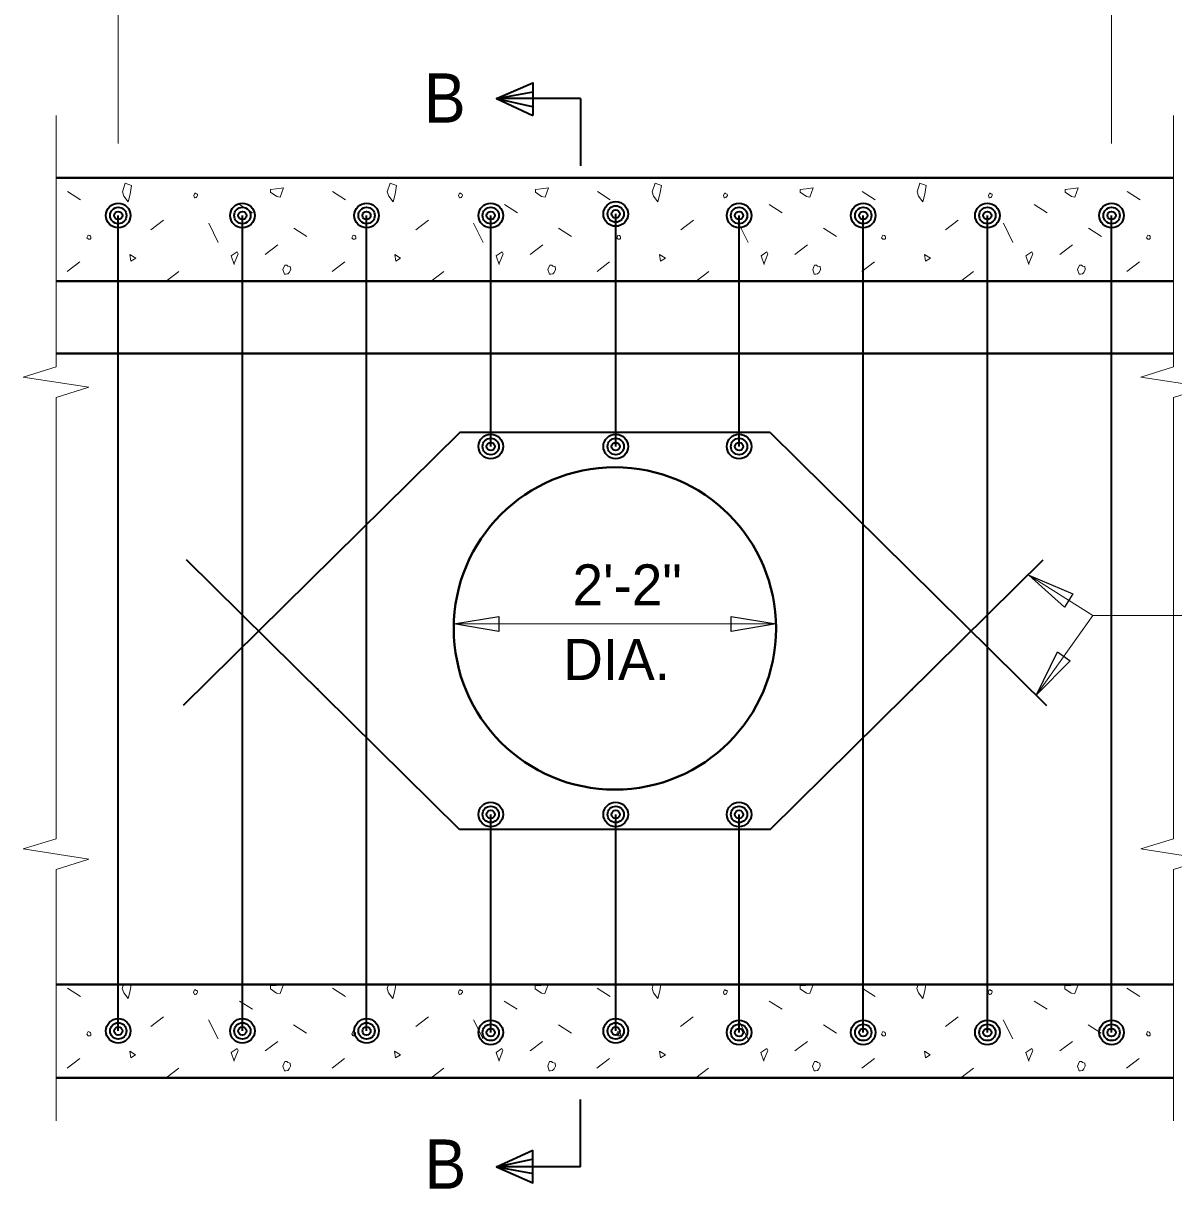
# Model space of a CAD drawing. Extents: x 0 to 34, y 0 to 23.4.
# Drawn here: x 25.268 to 29.648, y 4.725 to 9.162 of the extents above; entities that cross this region are included whole.
import ezdxf
from ezdxf.enums import TextEntityAlignment as Align

# ---------------------------------------------------------------- set-up
doc = ezdxf.new("R2010")
doc.units = 0
doc.header["$LTSCALE"] = 0.062
for name, color, linetype, lineweight in [('1', 7, 'Continuous', 40), ('3', 7, 'Continuous', 35), ('4', 7, 'Continuous', 13), ('7', 7, 'Continuous', 13)]:
    doc.layers.add(name, color=color, linetype=linetype, lineweight=lineweight)

msp = doc.modelspace()

# ---------------------------------------------------------------- linework, layer by layer
at = {"layer": '1', "lineweight": 13}
for p, q in [((25.39328, 7.85406), (25.39328, 8.81109)), ((29.6476, 7.85406), (29.6476, 8.81109)), ((25.39328, 6.05719), (25.39328, 7.73688)), ((29.6476, 6.05719), (29.6476, 7.73688)), ((25.39328, 4.98297), (25.39328, 5.94)), ((29.6476, 4.98297), (29.6476, 5.94))]:
    msp.add_line(p, q, dxfattribs=at)
at = {"layer": '1'}
for p, q in [((25.39328, 8.57406), (29.6476, 8.57406)), ((25.3937, 8.18005), (29.6476, 8.18005)), ((29.64682, 8.18005), (27.52672, 8.18005)), ((25.3937, 7.90438), (27.52042, 7.90438)), ((29.64682, 7.90438), (27.52042, 7.90438)), ((25.39328, 5.50151), (29.6476, 5.50151)), ((25.39328, 5.14703), (29.6476, 5.14703))]:
    msp.add_line(p, q, dxfattribs=at)
at = {"layer": '1', "lineweight": 13}
for points in [[(25.39328, 7.85406), (25.26828, 7.815), (25.51828, 7.77594), (25.39328, 7.73688)], [(29.6476, 7.85406), (29.5226, 7.815), (29.7726, 7.77594), (29.6476, 7.73688)], [(25.39328, 6.05719), (25.26828, 6.01813), (25.51828, 5.97906), (25.39328, 5.94)], [(29.6476, 6.05719), (29.5226, 6.01813), (29.7726, 5.97906), (29.6476, 5.94)]]:
    msp.add_lwpolyline(points, dxfattribs=at)
at = {"layer": '1'}
msp.add_circle((27.52044, 6.85779), 0.61354, dxfattribs=at)
at = {"layer": '3'}
for p, q in [((27.52354, 7.55063), (27.52354, 8.43589)), ((25.62969, 5.32536), (25.62969, 8.4301)), ((26.1024, 5.32536), (26.1024, 8.4301)), ((26.575, 5.32536), (26.575, 8.4301)), ((27.04776, 7.55063), (27.04776, 8.4301)), ((27.99313, 7.55063), (27.99313, 8.4301)), ((28.46583, 5.31958), (28.46583, 8.4301)), ((28.93844, 5.31958), (28.93844, 8.4301)), ((29.4112, 5.31958), (29.4112, 8.4301)), ((26.92964, 7.60354), (25.87693, 6.56458)), ((28.11125, 7.60354), (26.92964, 7.60354)), ((28.11125, 7.60354), (29.16396, 6.56458)), ((26.92943, 6.0924), (25.89005, 7.11849)), ((28.11135, 6.0924), (29.15083, 7.11849)), ((26.39016, 6.62484), (26.38792, 6.62698)), ((28.65073, 6.62484), (28.65292, 6.62698)), ((27.04776, 5.31958), (27.04776, 6.14974)), ((27.52354, 5.32536), (27.52354, 6.14974)), ((27.99313, 5.31958), (27.99313, 6.14974)), ((28.11135, 6.0924), (26.92943, 6.0924))]:
    msp.add_line(p, q, dxfattribs=at)
for centre, radius in [((25.62969, 8.4301), 0.04688), ((26.1024, 8.4301), 0.04688), ((26.575, 8.4301), 0.04688), ((27.04776, 8.4301), 0.04688), ((27.52354, 8.43589), 0.04688), ((27.99313, 8.4301), 0.04688), ((28.46583, 8.4301), 0.04688), ((28.93844, 8.4301), 0.04688), ((29.4112, 8.4301), 0.04688), ((25.62969, 8.4301), 0.03125), ((25.62969, 8.4301), 0.01562), ((26.1024, 8.4301), 0.03125), ((26.1024, 8.4301), 0.01562), ((26.575, 8.4301), 0.03125), ((26.575, 8.4301), 0.01562), ((27.04776, 8.4301), 0.03125), ((27.04776, 8.4301), 0.01562), ((27.52354, 8.43589), 0.03125), ((27.52354, 8.43589), 0.01562), ((27.99313, 8.4301), 0.03125), ((27.99313, 8.4301), 0.01562), ((28.46583, 8.4301), 0.03125), ((28.46583, 8.4301), 0.01562), ((28.93844, 8.4301), 0.03125), ((28.93844, 8.4301), 0.01562), ((29.4112, 8.4301), 0.03125), ((29.4112, 8.4301), 0.01562), ((27.04776, 7.55063), 0.04688), ((27.52354, 7.55063), 0.04688), ((27.99313, 7.55063), 0.04688), ((27.04776, 7.55063), 0.03125), ((27.04776, 7.55063), 0.01562), ((27.52354, 7.55063), 0.03125), ((27.52354, 7.55063), 0.01562), ((27.99313, 7.55063), 0.03125), ((27.99313, 7.55063), 0.01562), ((27.04776, 6.14974), 0.04688), ((27.04776, 6.14974), 0.03125), ((27.52354, 6.14974), 0.04688), ((27.52354, 6.14974), 0.03125), ((27.99313, 6.14974), 0.04688), ((27.99313, 6.14974), 0.03125), ((27.04776, 6.14974), 0.01562), ((27.52354, 6.14974), 0.01562), ((27.99313, 6.14974), 0.01562), ((25.62969, 5.32536), 0.04688), ((26.1024, 5.32536), 0.04688), ((26.575, 5.32536), 0.04688), ((27.52354, 5.32536), 0.04688), ((25.62969, 5.32536), 0.03125), ((25.62969, 5.32536), 0.01562), ((26.1024, 5.32536), 0.03125), ((26.1024, 5.32536), 0.01562), ((26.575, 5.32536), 0.03125), ((26.575, 5.32536), 0.01562), ((27.04776, 5.31958), 0.04688), ((27.04776, 5.31958), 0.03125), ((27.04776, 5.31958), 0.01562), ((27.52354, 5.32536), 0.03125), ((27.52354, 5.32536), 0.01562), ((27.99313, 5.31958), 0.04688), ((27.99313, 5.31958), 0.03125), ((27.99313, 5.31958), 0.01562), ((28.46583, 5.31958), 0.04688), ((28.46583, 5.31958), 0.03125), ((28.46583, 5.31958), 0.01562), ((28.93844, 5.31958), 0.04688), ((28.93844, 5.31958), 0.03125), ((28.93844, 5.31958), 0.01562), ((29.4112, 5.31958), 0.04688), ((29.4112, 5.31958), 0.03125), ((29.4112, 5.31958), 0.01562)]:
    msp.add_circle(centre, radius, dxfattribs=at)
at = {"layer": '4'}
for p, q in [((25.62969, 8.70458), (25.62969, 9.57755)), ((29.4112, 8.70458), (29.4112, 9.57755)), ((29.3401, 6.90651), (29.09609, 7.06089)), ((29.3401, 6.90651), (29.12505, 6.60469)), ((29.3401, 6.90651), (31.06495, 6.90651)), ((26.90703, 6.87505), (28.13385, 6.87505))]:
    msp.add_line(p, q, dxfattribs=at)
at = {"layer": '4', "lineweight": 35}
for p, q in [((27.06964, 8.87526), (27.20891, 8.90104)), ((27.06964, 8.87526), (27.20594, 8.84563)), ((27.38964, 8.87526), (27.38964, 8.61927)), ((27.38964, 4.80771), (27.38964, 5.0637)), ((27.06964, 4.80771), (27.20594, 4.83734)), ((27.06964, 4.80771), (27.20891, 4.78193))]:
    msp.add_line(p, q, dxfattribs=at)
for points in [[(27.06964, 8.87526), (27.20823, 8.93536), (27.20823, 8.81125)], [(27.38964, 8.87526), (27.06964, 8.87526), (27.20823, 8.81125)], [(27.38964, 4.80771), (27.06964, 4.80771), (27.20823, 4.87172)], [(27.06964, 4.80771), (27.20823, 4.7476), (27.20823, 4.87172)]]:
    msp.add_lwpolyline(points, dxfattribs=at)
at = {"layer": '4', "lineweight": 25}
for points in [[(29.26427, 6.99), (29.23219, 6.93927), (29.09609, 7.06089)], [(27.07802, 6.90354), (27.07802, 6.84656), (26.90703, 6.87505)], [(27.96286, 6.84656), (27.96286, 6.90354), (28.13385, 6.87505)], [(29.20505, 6.7687), (29.25396, 6.73385), (29.12505, 6.60469)]]:
    msp.add_lwpolyline(points, close=True, dxfattribs=at)
at = {"layer": '7'}
for p, q in [((25.43682, 8.52109), (25.48625, 8.48979)), ((26.44521, 8.52109), (26.49464, 8.48979)), ((27.45359, 8.52109), (27.50302, 8.48979)), ((28.46198, 8.52109), (28.51141, 8.48979)), ((29.47036, 8.52109), (29.51979, 8.48979)), ((26.09151, 8.47203), (26.14099, 8.44078)), ((27.0999, 8.47203), (27.14938, 8.44078)), ((28.10828, 8.47203), (28.15776, 8.44078)), ((29.11667, 8.47203), (29.16615, 8.44078)), ((25.80245, 8.41234), (25.75432, 8.37573)), ((25.97401, 8.40125), (26.01068, 8.32771)), ((26.81083, 8.41234), (26.76271, 8.37573)), ((26.9824, 8.40125), (27.01906, 8.32771)), ((27.81922, 8.41234), (27.77109, 8.37573)), ((27.99078, 8.40125), (28.02745, 8.32771)), ((28.8276, 8.41234), (28.77948, 8.37573)), ((28.99917, 8.40125), (29.03583, 8.32771)), ((26.29786, 8.38172), (26.34734, 8.35047)), ((27.30625, 8.38172), (27.35573, 8.35047)), ((28.31464, 8.38172), (28.36411, 8.35047)), ((29.32302, 8.38172), (29.3725, 8.35047)), ((26.2374, 8.31859), (26.18927, 8.28198)), ((27.24578, 8.31859), (27.19766, 8.28198)), ((28.25417, 8.31859), (28.20604, 8.28198)), ((29.26255, 8.31859), (29.21443, 8.28198)), ((25.48365, 8.25359), (25.43552, 8.21698)), ((26.49203, 8.25359), (26.44391, 8.21698)), ((27.50042, 8.25359), (27.45229, 8.21698)), ((28.5088, 8.25359), (28.46068, 8.21698)), ((29.51719, 8.25359), (29.46906, 8.21698)), ((25.86078, 8.21667), (25.81266, 8.18005)), ((26.86917, 8.21667), (26.82104, 8.18005)), ((27.87755, 8.21667), (27.82943, 8.18005)), ((28.88594, 8.21667), (28.83781, 8.18005)), ((25.43641, 5.48807), (25.48583, 5.45677)), ((26.25344, 5.50151), (26.23083, 5.49854)), ((26.44479, 5.48807), (26.49422, 5.45677)), ((27.26182, 5.50151), (27.23922, 5.49854)), ((27.45318, 5.48807), (27.5026, 5.45677)), ((28.27021, 5.50151), (28.2476, 5.49854)), ((28.46156, 5.48807), (28.51099, 5.45677)), ((29.27859, 5.50151), (29.25599, 5.49854)), ((29.46995, 5.48807), (29.51938, 5.45677)), ((26.09109, 5.43901), (26.14057, 5.40776)), ((27.09948, 5.43901), (27.14896, 5.40776)), ((28.10786, 5.43901), (28.15734, 5.40776)), ((29.11625, 5.43901), (29.16573, 5.40776)), ((25.80203, 5.37932), (25.75391, 5.34271)), ((26.81042, 5.37932), (26.76229, 5.34271)), ((27.8188, 5.37932), (27.77068, 5.34271)), ((28.82719, 5.37932), (28.77906, 5.34271)), ((25.97359, 5.36823), (26.01026, 5.29469)), ((26.29745, 5.3487), (26.34693, 5.31745)), ((26.98198, 5.36823), (27.01865, 5.29469)), ((27.30583, 5.3487), (27.35531, 5.31745)), ((27.99036, 5.36823), (28.02703, 5.29469)), ((28.31422, 5.3487), (28.3637, 5.31745)), ((28.99875, 5.36823), (29.03542, 5.29469)), ((29.3226, 5.3487), (29.37208, 5.31745)), ((26.23698, 5.28557), (26.18885, 5.24896)), ((27.24536, 5.28557), (27.19724, 5.24896)), ((28.25375, 5.28557), (28.20563, 5.24896)), ((29.26214, 5.28557), (29.21401, 5.24896)), ((25.48323, 5.22057), (25.4351, 5.18396)), ((26.49161, 5.22057), (26.44349, 5.18396)), ((27.5, 5.22057), (27.45188, 5.18396)), ((28.50839, 5.22057), (28.46026, 5.18396)), ((29.51677, 5.22057), (29.46865, 5.18396)), ((25.86036, 5.18365), (25.81224, 5.14703)), ((26.86875, 5.18365), (26.82063, 5.14703)), ((27.87714, 5.18365), (27.82901, 5.14703)), ((28.88552, 5.18365), (28.8374, 5.14703))]:
    msp.add_line(p, q, dxfattribs=at)
for points in [[(25.65661, 8.55349), (25.64542, 8.52036), (25.65109, 8.5038), (25.66766, 8.48167), (25.675, 8.51115), (25.68052, 8.54432)], [(26.23125, 8.53156), (26.20917, 8.52969), (26.20917, 8.51865), (26.23313, 8.50214), (26.24609, 8.50026), (26.25901, 8.53521)], [(26.665, 8.55349), (26.6538, 8.52036), (26.65948, 8.5038), (26.67604, 8.48167), (26.68339, 8.51115), (26.68891, 8.54432)], [(27.23964, 8.53156), (27.21755, 8.52969), (27.21755, 8.51865), (27.24151, 8.50214), (27.25448, 8.50026), (27.2674, 8.53521)], [(27.67339, 8.55349), (27.66219, 8.52036), (27.66786, 8.5038), (27.68443, 8.48167), (27.69177, 8.51115), (27.69729, 8.54432)], [(28.24802, 8.53156), (28.22594, 8.52969), (28.22594, 8.51865), (28.2499, 8.50214), (28.26286, 8.50026), (28.27578, 8.53521)], [(28.68177, 8.55349), (28.67057, 8.52036), (28.67625, 8.5038), (28.69281, 8.48167), (28.70016, 8.51115), (28.70568, 8.54432)], [(29.25641, 8.53156), (29.23432, 8.52969), (29.23432, 8.51865), (29.25828, 8.50214), (29.27125, 8.50026), (29.28417, 8.53521)], [(25.91703, 8.50625), (25.91995, 8.49703), (25.9226, 8.49703), (25.92635, 8.49797), (25.92906, 8.50063), (25.93172, 8.50625), (25.93099, 8.51177), (25.92635, 8.51271), (25.92438, 8.51464), (25.92073, 8.51464)], [(26.92542, 8.50625), (26.92833, 8.49703), (26.93099, 8.49703), (26.93474, 8.49797), (26.93745, 8.50063), (26.9401, 8.50625), (26.93938, 8.51177), (26.93474, 8.51271), (26.93276, 8.51464), (26.92911, 8.51464)], [(27.9338, 8.50625), (27.93672, 8.49703), (27.93938, 8.49703), (27.94313, 8.49797), (27.94583, 8.50063), (27.94849, 8.50625), (27.94776, 8.51177), (27.94313, 8.51271), (27.94115, 8.51464), (27.9375, 8.51464)], [(28.94219, 8.50625), (28.9451, 8.49703), (28.94776, 8.49703), (28.95151, 8.49797), (28.95422, 8.50063), (28.95688, 8.50625), (28.95615, 8.51177), (28.95151, 8.51271), (28.94953, 8.51464), (28.94589, 8.51464)], [(25.5151, 8.35562), (25.51047, 8.34547), (25.51589, 8.33984), (25.5225, 8.33984), (25.52521, 8.34281), (25.52521, 8.34823), (25.52432, 8.35089), (25.52146, 8.35385)], [(26.52349, 8.35562), (26.51885, 8.34547), (26.52427, 8.33984), (26.53089, 8.33984), (26.53359, 8.34281), (26.53359, 8.34823), (26.53271, 8.35089), (26.52984, 8.35385)], [(27.53188, 8.35562), (27.52724, 8.34547), (27.53266, 8.33984), (27.53927, 8.33984), (27.54198, 8.34281), (27.54198, 8.34823), (27.54109, 8.35089), (27.53823, 8.35385)], [(28.54026, 8.35562), (28.53563, 8.34547), (28.54104, 8.33984), (28.54766, 8.33984), (28.55036, 8.34281), (28.55036, 8.34823), (28.54948, 8.35089), (28.54661, 8.35385)], [(29.54865, 8.35562), (29.54401, 8.34547), (29.54943, 8.33984), (29.55604, 8.33984), (29.55875, 8.34281), (29.55875, 8.34823), (29.55786, 8.35089), (29.555, 8.35385)], [(25.67401, 8.28188), (25.67771, 8.25604), (25.6962, 8.26714)], [(26.06005, 8.27646), (26.07146, 8.24323), (26.07146, 8.24682), (26.08615, 8.2838), (26.0824, 8.29115)], [(26.6824, 8.28188), (26.68609, 8.25604), (26.70458, 8.26714)], [(27.06844, 8.27646), (27.07984, 8.24323), (27.07984, 8.24682), (27.09453, 8.2838), (27.09078, 8.29115)], [(27.69078, 8.28188), (27.69448, 8.25604), (27.71297, 8.26714)], [(28.07682, 8.27646), (28.08823, 8.24323), (28.08823, 8.24682), (28.10292, 8.2838), (28.09917, 8.29115)], [(28.69917, 8.28188), (28.70286, 8.25604), (28.72135, 8.26714)], [(29.08521, 8.27646), (29.09661, 8.24323), (29.09661, 8.24682), (29.1113, 8.2838), (29.10755, 8.29115)], [(26.25667, 8.22474), (26.2625, 8.2063), (26.26781, 8.2063), (26.27531, 8.20813), (26.28073, 8.21349), (26.28609, 8.22474), (26.28458, 8.23568), (26.27531, 8.2376), (26.27141, 8.24141), (26.26406, 8.24141)], [(27.26505, 8.22474), (27.27089, 8.2063), (27.2762, 8.2063), (27.2837, 8.20813), (27.28911, 8.21349), (27.29448, 8.22474), (27.29297, 8.23568), (27.2837, 8.2376), (27.27979, 8.24141), (27.27245, 8.24141)], [(28.27344, 8.22474), (28.27927, 8.2063), (28.28458, 8.2063), (28.29208, 8.20813), (28.2975, 8.21349), (28.30286, 8.22474), (28.30135, 8.23568), (28.29208, 8.2376), (28.28818, 8.24141), (28.28083, 8.24141)], [(29.28182, 8.22474), (29.28766, 8.2063), (29.29297, 8.2063), (29.30047, 8.20813), (29.30589, 8.21349), (29.31125, 8.22474), (29.30974, 8.23568), (29.30047, 8.2376), (29.29656, 8.24141), (29.28922, 8.24141)], [(25.91661, 5.47323), (25.91953, 5.46401), (25.92219, 5.46401), (25.92594, 5.46495), (25.92865, 5.4676), (25.9313, 5.47323), (25.93057, 5.47875), (25.92594, 5.47969), (25.92396, 5.48161), (25.92031, 5.48161)], [(26.925, 5.47323), (26.92792, 5.46401), (26.93057, 5.46401), (26.93432, 5.46495), (26.93703, 5.4676), (26.93969, 5.47323), (26.93896, 5.47875), (26.93432, 5.47969), (26.93234, 5.48161), (26.9287, 5.48161)], [(27.93339, 5.47323), (27.9363, 5.46401), (27.93896, 5.46401), (27.94271, 5.46495), (27.94542, 5.4676), (27.94807, 5.47323), (27.94734, 5.47875), (27.94271, 5.47969), (27.94073, 5.48161), (27.93708, 5.48161)], [(28.94177, 5.47323), (28.94469, 5.46401), (28.94734, 5.46401), (28.95109, 5.46495), (28.9538, 5.4676), (28.95646, 5.47323), (28.95573, 5.47875), (28.95109, 5.47969), (28.94911, 5.48161), (28.94547, 5.48161)], [(25.51469, 5.3226), (25.51005, 5.31245), (25.51547, 5.30682), (25.52208, 5.30682), (25.52479, 5.30979), (25.52479, 5.31521), (25.52391, 5.31786), (25.52104, 5.32083)], [(26.52307, 5.3226), (26.51844, 5.31245), (26.52385, 5.30682), (26.53047, 5.30682), (26.53318, 5.30979), (26.53318, 5.31521), (26.53229, 5.31786), (26.52943, 5.32083)], [(27.53146, 5.3226), (27.52682, 5.31245), (27.53224, 5.30682), (27.53885, 5.30682), (27.54156, 5.30979), (27.54156, 5.31521), (27.54068, 5.31786), (27.53781, 5.32083)], [(28.53984, 5.3226), (28.53521, 5.31245), (28.54063, 5.30682), (28.54724, 5.30682), (28.54995, 5.30979), (28.54995, 5.31521), (28.54906, 5.31786), (28.5462, 5.32083)], [(29.54823, 5.3226), (29.54359, 5.31245), (29.54901, 5.30682), (29.55563, 5.30682), (29.55833, 5.30979), (29.55833, 5.31521), (29.55745, 5.31786), (29.55458, 5.32083)], [(25.67359, 5.24885), (25.67729, 5.22302), (25.69578, 5.23411)], [(26.05964, 5.24344), (26.07104, 5.21021), (26.07104, 5.2138), (26.08573, 5.25078), (26.08198, 5.25813)], [(26.68198, 5.24885), (26.68568, 5.22302), (26.70417, 5.23411)], [(27.06802, 5.24344), (27.07943, 5.21021), (27.07943, 5.2138), (27.09411, 5.25078), (27.09036, 5.25813)], [(27.69036, 5.24885), (27.69406, 5.22302), (27.71255, 5.23411)], [(28.07641, 5.24344), (28.08781, 5.21021), (28.08781, 5.2138), (28.1025, 5.25078), (28.09875, 5.25813)], [(28.69875, 5.24885), (28.70245, 5.22302), (28.72094, 5.23411)], [(29.08479, 5.24344), (29.0962, 5.21021), (29.0962, 5.2138), (29.11089, 5.25078), (29.10714, 5.25813)], [(26.25625, 5.19172), (26.26208, 5.17328), (26.2674, 5.17328), (26.2749, 5.1751), (26.28031, 5.18047), (26.28568, 5.19172), (26.28417, 5.20266), (26.2749, 5.20458), (26.27099, 5.20839), (26.26365, 5.20839)], [(27.26464, 5.19172), (27.27047, 5.17328), (27.27578, 5.17328), (27.28328, 5.1751), (27.2887, 5.18047), (27.29406, 5.19172), (27.29255, 5.20266), (27.28328, 5.20458), (27.27938, 5.20839), (27.27203, 5.20839)], [(28.27302, 5.19172), (28.27885, 5.17328), (28.28417, 5.17328), (28.29167, 5.1751), (28.29708, 5.18047), (28.30245, 5.19172), (28.30094, 5.20266), (28.29167, 5.20458), (28.28776, 5.20839), (28.28042, 5.20839)], [(29.28141, 5.19172), (29.28724, 5.17328), (29.29255, 5.17328), (29.30005, 5.1751), (29.30547, 5.18047), (29.31083, 5.19172), (29.30932, 5.20266), (29.30005, 5.20458), (29.29615, 5.20839), (29.2888, 5.20839)]]:
    msp.add_lwpolyline(points, close=True, dxfattribs=at)
for points in [[(25.64979, 5.50151), (25.645, 5.48734), (25.65068, 5.47078), (25.66724, 5.44865), (25.67458, 5.47813), (25.67849, 5.50151)], [(26.23083, 5.49854), (26.20875, 5.49667), (26.20875, 5.48563), (26.23271, 5.46911), (26.24568, 5.46724), (26.25833, 5.50151)], [(26.65818, 5.50151), (26.65339, 5.48734), (26.65906, 5.47078), (26.67563, 5.44865), (26.68297, 5.47813), (26.68688, 5.50151)], [(27.23922, 5.49854), (27.21714, 5.49667), (27.21714, 5.48563), (27.24109, 5.46911), (27.25406, 5.46724), (27.26672, 5.50151)], [(27.66656, 5.50151), (27.66177, 5.48734), (27.66745, 5.47078), (27.68401, 5.44865), (27.69135, 5.47813), (27.69526, 5.50151)], [(28.2476, 5.49854), (28.22552, 5.49667), (28.22552, 5.48563), (28.24948, 5.46911), (28.26245, 5.46724), (28.2751, 5.50151)], [(28.67495, 5.50151), (28.67016, 5.48734), (28.67583, 5.47078), (28.6924, 5.44865), (28.69974, 5.47813), (28.70365, 5.50151)], [(29.25599, 5.49854), (29.23391, 5.49667), (29.23391, 5.48563), (29.25786, 5.46911), (29.27083, 5.46724), (29.28349, 5.50151)]]:
    msp.add_lwpolyline(points, dxfattribs=at)

# ---------------------------------------------------------------- texts
at = {"layer": '4', "width": 0.95}
for p in [(26.95224, 8.7837), (26.95458, 4.72469)]:
    msp.add_text('B', height=0.1875, dxfattribs=at).set_placement(p, align=Align.RIGHT)
at = {"layer": '4'}
for s, p in [('2\'-2"', (27.56708, 6.94552)), ('DIA.', (27.52693, 6.66156))]:
    msp.add_text(s, height=0.1563, dxfattribs=at).set_placement(p, align=Align.CENTER)

doc.saveas('drawing.dxf')
